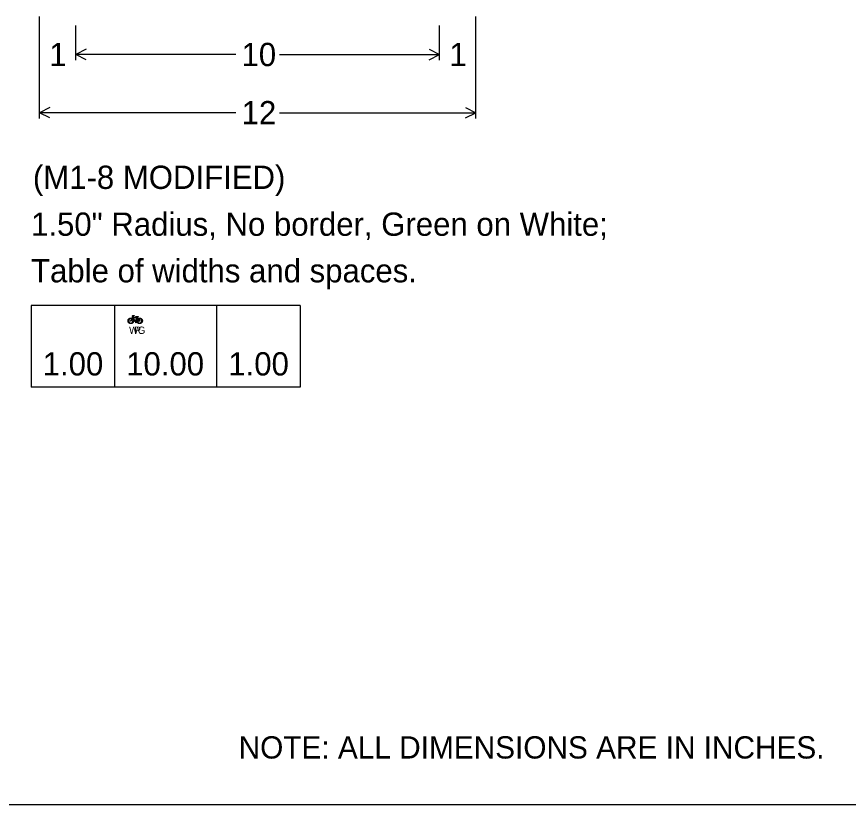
# Model space of a CAD drawing. Extents: x -39.4 to 36.9, y -12.9 to 28.
# Drawn here: x -12.53 to -7.31, y -1.19 to 3.76 of the extents above; entities that cross this region are included whole.
import ezdxf

# ---------------------------------------------------------------- set-up
doc = ezdxf.new("R2010")
doc.units = 0
doc.layers.add('PM_P_Text', color=7, linetype='Continuous')
doc.layers.add('SH_Text', color=7, linetype='Continuous')

msp = doc.modelspace()

# ---------------------------------------------------------------- linework, layer by layer
at = {"layer": 'PM_P_Text'}
for p, q in [((-12.3914, 3.1166), (-12.3914, 3.7566)), ((-9.6482, 3.1166), (-9.6482, 3.7566)), ((-12.3914, 3.4823), (-12.3914, 3.7018)), ((-12.1628, 3.4823), (-12.1628, 3.7018)), ((-9.8768, 3.4823), (-9.8768, 3.7018)), ((-9.8768, 3.4823), (-9.8768, 3.7018)), ((-9.6482, 3.4823), (-9.6482, 3.7018)), ((-12.0973, 3.5516), (-12.1628, 3.5189)), ((-11.1575, 3.5189), (-12.1628, 3.5189)), ((-12.0973, 3.4862), (-12.1628, 3.5189)), ((-10.8821, 3.5189), (-9.8768, 3.5189)), ((-9.9422, 3.5516), (-9.8768, 3.5189)), ((-9.9422, 3.4862), (-9.8768, 3.5189)), ((-12.3259, 3.1858), (-12.3914, 3.1531)), ((-11.1567, 3.1531), (-12.3914, 3.1531)), ((-12.3259, 3.1204), (-12.3914, 3.1531)), ((-10.8828, 3.1531), (-9.6482, 3.1531)), ((-9.7136, 3.1858), (-9.6482, 3.1531)), ((-9.7136, 3.1204), (-9.6482, 3.1531)), ((-12.4437, 1.9405), (-12.4437, 1.4284)), ((-10.7524, 1.9405), (-12.4437, 1.9405)), ((-11.919, 1.9405), (-11.919, 1.4284)), ((-11.2771, 1.9405), (-11.2771, 1.4284)), ((-10.7524, 1.9405), (-10.7524, 1.4284)), ((-10.7524, 1.4284), (-12.4437, 1.4284))]:
    msp.add_line(p, q, dxfattribs=at)
for points in [[(-11.8231, 1.8285), (-11.8236, 1.8287), (-11.8241, 1.8289), (-11.8246, 1.8291), (-11.8251, 1.8294), (-11.8256, 1.8297), (-11.8261, 1.83), (-11.8265, 1.8303), (-11.827, 1.8306), (-11.8275, 1.831), (-11.8279, 1.8313), (-11.8284, 1.8317), (-11.8288, 1.8321), (-11.8292, 1.8325), (-11.8296, 1.833), (-11.8301, 1.8334), (-11.8304, 1.8338), (-11.8308, 1.8343), (-11.8311, 1.8348), (-11.8315, 1.8352), (-11.8318, 1.8357), (-11.8321, 1.8362), (-11.8323, 1.8367), (-11.8326, 1.8372), (-11.8328, 1.8377), (-11.8331, 1.8382), (-11.8333, 1.8387), (-11.8335, 1.8392), (-11.8336, 1.8398), (-11.8338, 1.8403), (-11.8339, 1.8409), (-11.834, 1.8414), (-11.8341, 1.842), (-11.8342, 1.8426), (-11.8343, 1.8432), (-11.8343, 1.8437), (-11.8343, 1.8443), (-11.8343, 1.8449), (-11.8343, 1.8455), (-11.8343, 1.8461), (-11.8343, 1.8467), (-11.8342, 1.8473), (-11.8341, 1.8479), (-11.834, 1.8484), (-11.8339, 1.849), (-11.8338, 1.8495), (-11.8336, 1.8501), (-11.8335, 1.8506), (-11.8333, 1.8511), (-11.8331, 1.8517), (-11.8328, 1.8522), (-11.8326, 1.8527), (-11.8323, 1.8532), (-11.8321, 1.8536), (-11.8318, 1.8541), (-11.8315, 1.8546), (-11.8311, 1.8551), (-11.8308, 1.8555), (-11.8304, 1.856), (-11.83, 1.8565), (-11.8296, 1.8569), (-11.8292, 1.8573), (-11.8288, 1.8577), (-11.8284, 1.8581), (-11.8279, 1.8585), (-11.8275, 1.8589), (-11.827, 1.8592), (-11.8265, 1.8596), (-11.8261, 1.8599), (-11.8256, 1.8602), (-11.8251, 1.8605), (-11.8246, 1.8607), (-11.8241, 1.861), (-11.8236, 1.8612), (-11.8231, 1.8614), (-11.8225, 1.8616), (-11.822, 1.8617), (-11.8215, 1.8619), (-11.8209, 1.862), (-11.8204, 1.8622), (-11.8198, 1.8622), (-11.8192, 1.8623), (-11.8187, 1.8624), (-11.8181, 1.8624), (-11.8175, 1.8625), (-11.8169, 1.8625), (-11.8159, 1.8624), (-11.815, 1.8624), (-11.814, 1.8622), (-11.8131, 1.8621), (-11.8122, 1.8618), (-11.8113, 1.8615), (-11.8104, 1.8612), (-11.8095, 1.8608), (-11.8087, 1.8603), (-11.8043, 1.8734), (-11.8045, 1.8735), (-11.8047, 1.8737), (-11.8049, 1.874), (-11.8052, 1.8743), (-11.8055, 1.8747)], [(-11.828, 1.8535), (-11.8283, 1.853), (-11.8286, 1.8525), (-11.8289, 1.852), (-11.8292, 1.8516), (-11.8295, 1.851), (-11.8297, 1.8505), (-11.8299, 1.85), (-11.8301, 1.8495), (-11.8303, 1.8489), (-11.8305, 1.8484), (-11.8306, 1.8478), (-11.8307, 1.8472), (-11.8308, 1.8467), (-11.8308, 1.8461), (-11.8309, 1.8455), (-11.8309, 1.8449), (-11.8309, 1.8443), (-11.8308, 1.8437), (-11.8308, 1.8431), (-11.8307, 1.8425), (-11.8306, 1.8419), (-11.8305, 1.8414), (-11.8303, 1.8408), (-11.8301, 1.8403), (-11.8299, 1.8397), (-11.8297, 1.8392), (-11.8295, 1.8387), (-11.8292, 1.8382), (-11.8289, 1.8377), (-11.8286, 1.8372), (-11.8283, 1.8368), (-11.828, 1.8363), (-11.8276, 1.8358), (-11.8272, 1.8354), (-11.8268, 1.8349), (-11.8263, 1.8345), (-11.8259, 1.8341), (-11.8254, 1.8338), (-11.825, 1.8334), (-11.8245, 1.8331), (-11.824, 1.8328), (-11.8235, 1.8325), (-11.823, 1.8322), (-11.8225, 1.832), (-11.822, 1.8318), (-11.8214, 1.8316), (-11.8209, 1.8314), (-11.8203, 1.8312), (-11.8198, 1.8311), (-11.8192, 1.831), (-11.8187, 1.8309), (-11.8181, 1.8309), (-11.8175, 1.8309), (-11.8168, 1.8308), (-11.8163, 1.8309), (-11.8157, 1.8309), (-11.8151, 1.8309), (-11.8145, 1.831), (-11.8139, 1.8311), (-11.8134, 1.8312), (-11.8128, 1.8314), (-11.8123, 1.8316), (-11.8118, 1.8317), (-11.8112, 1.832), (-11.8107, 1.8322), (-11.8102, 1.8325), (-11.8097, 1.8328), (-11.8093, 1.8331), (-11.8088, 1.8334), (-11.8083, 1.8337), (-11.8079, 1.8341), (-11.8074, 1.8345), (-11.807, 1.8349), (-11.8066, 1.8354), (-11.8062, 1.8358), (-11.8058, 1.8363), (-11.8054, 1.8367), (-11.8051, 1.8372), (-11.8048, 1.8377), (-11.8045, 1.8382), (-11.8043, 1.8387), (-11.804, 1.8392), (-11.8038, 1.8397), (-11.8036, 1.8403), (-11.8034, 1.8408), (-11.8033, 1.8413), (-11.8032, 1.8419), (-11.8031, 1.8424), (-11.803, 1.843), (-11.8029, 1.8436), (-11.8029, 1.8442), (-11.8029, 1.8448), (-11.8029, 1.8454), (-11.8029, 1.846), (-11.803, 1.8465), (-11.8031, 1.8471), (-11.8032, 1.8476), (-11.8032, 1.8482), (-11.8034, 1.8487), (-11.8035, 1.8492)], [(-11.8074, 1.8551), (-11.8075, 1.8546), (-11.8077, 1.8542), (-11.8079, 1.8538), (-11.808, 1.8535), (-11.8081, 1.8532), (-11.8082, 1.853), (-11.8082, 1.8528), (-11.8083, 1.8527), (-11.8083, 1.8527), (-11.8088, 1.8518), (-11.8095, 1.8508), (-11.8101, 1.85), (-11.8108, 1.8491), (-11.8117, 1.8481), (-11.8119, 1.8479), (-11.8121, 1.8477), (-11.8124, 1.8474), (-11.8128, 1.8471), (-11.8132, 1.8467), (-11.8137, 1.8462), (-11.814, 1.8459), (-11.8143, 1.8456), (-11.8146, 1.8453), (-11.8147, 1.8452), (-11.8148, 1.8451), (-11.8149, 1.845), (-11.815, 1.8442), (-11.8155, 1.8435), (-11.8161, 1.8431), (-11.8169, 1.8429), (-11.8175, 1.8431), (-11.8181, 1.8434), (-11.8185, 1.8439), (-11.8187, 1.8446), (-11.8186, 1.8449), (-11.8186, 1.8452), (-11.8185, 1.8455), (-11.8183, 1.8458), (-11.8182, 1.846), (-11.8179, 1.8462), (-11.8177, 1.8464), (-11.8174, 1.8465), (-11.8171, 1.8466), (-11.8167, 1.8467), (-11.8163, 1.8469), (-11.8159, 1.8472), (-11.8154, 1.8476), (-11.815, 1.848), (-11.8145, 1.8486), (-11.814, 1.8492), (-11.8136, 1.8496), (-11.8133, 1.8501), (-11.8128, 1.8508), (-11.8123, 1.8515), (-11.8117, 1.8523), (-11.8115, 1.8525), (-11.8113, 1.853), (-11.811, 1.8535), (-11.8108, 1.8542), (-11.8107, 1.8543), (-11.8107, 1.8544), (-11.8106, 1.8546), (-11.8106, 1.8548), (-11.8105, 1.8551), (-11.8104, 1.8554), (-11.8103, 1.8557), (-11.8102, 1.8561), (-11.81, 1.8566), (-11.8099, 1.8571), (-11.8107, 1.8575), (-11.8115, 1.8579), (-11.8124, 1.8582), (-11.8132, 1.8584), (-11.8141, 1.8587), (-11.815, 1.8588), (-11.8159, 1.8589), (-11.8168, 1.8589), (-11.8174, 1.8589), (-11.8181, 1.8589), (-11.8186, 1.8588), (-11.8192, 1.8587), (-11.8198, 1.8586), (-11.8203, 1.8585), (-11.8209, 1.8584), (-11.8214, 1.8582), (-11.822, 1.858), (-11.8225, 1.8578), (-11.823, 1.8575), (-11.8235, 1.8573), (-11.824, 1.857), (-11.8245, 1.8567), (-11.825, 1.8563), (-11.8254, 1.856), (-11.8259, 1.8556), (-11.8263, 1.8552), (-11.8268, 1.8548), (-11.8272, 1.8544), (-11.8276, 1.8539), (-11.828, 1.8535)], [(-11.7867, 1.8383), (-11.7872, 1.8384), (-11.7876, 1.8387), (-11.7879, 1.839), (-11.7882, 1.8394), (-11.7883, 1.8399), (-11.7884, 1.8405), (-11.7884, 1.841), (-11.8057, 1.86), (-11.8061, 1.8587), (-11.8057, 1.8584), (-11.8053, 1.858), (-11.8049, 1.8577), (-11.8045, 1.8573), (-11.8042, 1.857), (-11.8038, 1.8566), (-11.8035, 1.8562), (-11.8032, 1.8558), (-11.8029, 1.8555), (-11.8026, 1.8551), (-11.8023, 1.8547), (-11.802, 1.8543), (-11.8018, 1.8539), (-11.8015, 1.8535), (-11.8013, 1.853), (-11.8011, 1.8526), (-11.8009, 1.8522), (-11.8007, 1.8517), (-11.8005, 1.8513), (-11.8004, 1.8508), (-11.8002, 1.8504), (-11.8001, 1.8499), (-11.8, 1.8494), (-11.7998, 1.849), (-11.7997, 1.8485), (-11.7997, 1.848), (-11.7996, 1.8475), (-11.7995, 1.847), (-11.7995, 1.8465), (-11.7994, 1.846), (-11.7994, 1.8454), (-11.7994, 1.8449), (-11.7994, 1.8443), (-11.7994, 1.8437), (-11.7995, 1.8431), (-11.7996, 1.8425), (-11.7996, 1.842), (-11.7997, 1.8414), (-11.7998, 1.8408), (-11.8, 1.8403), (-11.8001, 1.8398), (-11.8003, 1.8392), (-11.8005, 1.8387), (-11.8007, 1.8382), (-11.8009, 1.8377), (-11.8012, 1.8372), (-11.8014, 1.8367), (-11.8017, 1.8362), (-11.802, 1.8357), (-11.8023, 1.8352), (-11.8026, 1.8347), (-11.803, 1.8343), (-11.8033, 1.8338), (-11.8037, 1.8334), (-11.8041, 1.833), (-11.8045, 1.8325), (-11.805, 1.8321), (-11.8054, 1.8317), (-11.8058, 1.8313), (-11.8063, 1.831), (-11.8067, 1.8306), (-11.8072, 1.8303), (-11.8077, 1.83), (-11.8082, 1.8297), (-11.8087, 1.8294), (-11.8092, 1.8291), (-11.8097, 1.8289), (-11.8102, 1.8287), (-11.8107, 1.8285), (-11.8112, 1.8283), (-11.8117, 1.8281), (-11.8123, 1.828), (-11.8128, 1.8278), (-11.8134, 1.8277), (-11.814, 1.8276), (-11.8145, 1.8275), (-11.8151, 1.8275), (-11.8157, 1.8274), (-11.8163, 1.8274), (-11.8169, 1.8274), (-11.8175, 1.8274), (-11.8181, 1.8274), (-11.8187, 1.8275), (-11.8192, 1.8275), (-11.8198, 1.8276), (-11.8204, 1.8277), (-11.8209, 1.8278), (-11.8215, 1.828), (-11.822, 1.8281), (-11.8226, 1.8283), (-11.8231, 1.8285)], [(-11.8035, 1.8492), (-11.8037, 1.8497), (-11.8039, 1.8502), (-11.8041, 1.8507), (-11.8043, 1.8512), (-11.8046, 1.8516), (-11.8049, 1.8521), (-11.8052, 1.8525), (-11.8055, 1.853), (-11.8058, 1.8534), (-11.8062, 1.8539), (-11.8065, 1.8543), (-11.8069, 1.8547), (-11.8074, 1.8551), (-11.8074, 1.8551)], [(-11.8055, 1.8747), (-11.8059, 1.8751), (-11.8064, 1.8756), (-11.8031, 1.8787), (-11.7953, 1.8787), (-11.7953, 1.8778), (-11.7953, 1.877), (-11.7953, 1.8765), (-11.8018, 1.8765), (-11.8029, 1.8753), (-11.8009, 1.8733), (-11.803, 1.8672), (-11.7789, 1.8672), (-11.7786, 1.868), (-11.7783, 1.8688), (-11.7786, 1.8688), (-11.779, 1.8689), (-11.7794, 1.869), (-11.78, 1.8691), (-11.7807, 1.8692), (-11.7813, 1.8694), (-11.7821, 1.8696), (-11.7831, 1.8699), (-11.7842, 1.8703), (-11.7846, 1.8706), (-11.7849, 1.871), (-11.785, 1.8713), (-11.7849, 1.8717), (-11.7848, 1.8719), (-11.7845, 1.872), (-11.7842, 1.8721), (-11.7709, 1.8729), (-11.7706, 1.8729), (-11.7703, 1.8729), (-11.7701, 1.8728), (-11.77, 1.8726), (-11.7699, 1.8724), (-11.7698, 1.8721), (-11.7699, 1.8718), (-11.77, 1.8715), (-11.7703, 1.8711), (-11.7707, 1.8707), (-11.7711, 1.8704), (-11.7717, 1.8701), (-11.7722, 1.8698), (-11.7729, 1.8695), (-11.7736, 1.8692), (-11.7745, 1.8689), (-11.7749, 1.8688), (-11.7753, 1.8686), (-11.7761, 1.8662), (-11.7757, 1.8657), (-11.7754, 1.8653), (-11.775, 1.8648), (-11.7746, 1.8643), (-11.7742, 1.8637), (-11.7737, 1.8631), (-11.7732, 1.8625), (-11.7727, 1.8618), (-11.7722, 1.8611), (-11.7716, 1.8604), (-11.771, 1.8596), (-11.771, 1.8596)], [(-11.7797, 1.8645), (-11.8041, 1.8645), (-11.8045, 1.8632), (-11.7877, 1.8445), (-11.7882, 1.8472), (-11.7895, 1.8472), (-11.7895, 1.8487), (-11.7855, 1.8487), (-11.7855, 1.8472), (-11.7866, 1.8472), (-11.7865, 1.8465), (-11.7864, 1.8459), (-11.7863, 1.8455), (-11.7862, 1.8451), (-11.7861, 1.8447), (-11.7861, 1.8445), (-11.7797, 1.8645), (-11.7797, 1.8645)], [(-11.7558, 1.8285), (-11.7563, 1.8283), (-11.7568, 1.8282), (-11.7574, 1.828), (-11.7579, 1.8279), (-11.7585, 1.8278), (-11.7591, 1.8277), (-11.7596, 1.8277), (-11.7602, 1.8276), (-11.7608, 1.8276), (-11.7614, 1.8276), (-11.7622, 1.8276), (-11.7629, 1.8277), (-11.7636, 1.8277), (-11.7643, 1.8278), (-11.765, 1.8279), (-11.7657, 1.8281), (-11.7664, 1.8283), (-11.7671, 1.8285), (-11.7677, 1.8287), (-11.7684, 1.829), (-11.769, 1.8293), (-11.7696, 1.8296), (-11.7703, 1.8299), (-11.7709, 1.8303), (-11.7714, 1.8307), (-11.772, 1.8312), (-11.7726, 1.8316), (-11.7732, 1.8321), (-11.7737, 1.8326), (-11.7742, 1.8331), (-11.7746, 1.8336), (-11.7751, 1.8341), (-11.7755, 1.8347), (-11.7759, 1.8352), (-11.7763, 1.8358), (-11.7767, 1.8364), (-11.777, 1.8371), (-11.7773, 1.8377), (-11.7775, 1.8383), (-11.7778, 1.839), (-11.7781, 1.8397), (-11.7783, 1.8403), (-11.7789, 1.8402), (-11.7797, 1.8401), (-11.7806, 1.84), (-11.7815, 1.8398), (-11.7825, 1.8396), (-11.7835, 1.8394), (-11.7838, 1.8391), (-11.7842, 1.8387), (-11.7844, 1.8386), (-11.7847, 1.8385), (-11.7847, 1.8385), (-11.7847, 1.8384), (-11.7847, 1.8384), (-11.7847, 1.8383), (-11.7846, 1.8382), (-11.7846, 1.8381), (-11.7846, 1.8379), (-11.7845, 1.8377), (-11.7845, 1.8375), (-11.7844, 1.8373), (-11.7844, 1.8371), (-11.7843, 1.8368), (-11.7842, 1.8365), (-11.7842, 1.8362), (-11.7841, 1.8359), (-11.784, 1.8356), (-11.7839, 1.8352), (-11.7838, 1.8348), (-11.7837, 1.8344), (-11.7836, 1.8339), (-11.7835, 1.8335), (-11.7821, 1.8335), (-11.7821, 1.8318), (-11.7861, 1.8318), (-11.7861, 1.8335), (-11.7853, 1.8335), (-11.7853, 1.8335), (-11.7853, 1.8335), (-11.7853, 1.8336), (-11.7853, 1.8336), (-11.7853, 1.8337), (-11.7853, 1.8339), (-11.7854, 1.834), (-11.7854, 1.8342), (-11.7855, 1.8343), (-11.7855, 1.8345), (-11.7855, 1.8348), (-11.7856, 1.835), (-11.7857, 1.8353), (-11.7857, 1.8356), (-11.7858, 1.8359), (-11.7859, 1.8362), (-11.786, 1.8365), (-11.7861, 1.8369), (-11.7861, 1.8373), (-11.7863, 1.8377), (-11.7863, 1.8382), (-11.7867, 1.8383)], [(-11.7835, 1.8425), (-11.7789, 1.8432), (-11.7789, 1.8442), (-11.7789, 1.845), (-11.7789, 1.8456), (-11.7789, 1.8461), (-11.7789, 1.8467), (-11.7788, 1.8473), (-11.7787, 1.8478), (-11.7786, 1.8484), (-11.7785, 1.8489), (-11.7784, 1.8494), (-11.7783, 1.85), (-11.7781, 1.8505), (-11.7779, 1.851), (-11.7777, 1.8515), (-11.7775, 1.852), (-11.7773, 1.8525), (-11.7771, 1.8529), (-11.7768, 1.8534), (-11.7765, 1.8539), (-11.7762, 1.8544), (-11.7759, 1.8548), (-11.7756, 1.8552), (-11.7753, 1.8557), (-11.7749, 1.8561), (-11.7745, 1.8565), (-11.7741, 1.857), (-11.7737, 1.8574), (-11.7733, 1.8578), (-11.7771, 1.8628), (-11.7835, 1.8425), (-11.7835, 1.8425)], [(-11.7642, 1.846), (-11.7643, 1.8462), (-11.7645, 1.8465), (-11.7647, 1.8467), (-11.7649, 1.847), (-11.7652, 1.8473), (-11.7654, 1.8476), (-11.7657, 1.8479), (-11.7659, 1.8483), (-11.7662, 1.8486), (-11.7665, 1.849), (-11.7668, 1.8494), (-11.7671, 1.8498), (-11.7675, 1.8503), (-11.7678, 1.8507), (-11.7682, 1.8512), (-11.7685, 1.8517), (-11.7689, 1.8522), (-11.7693, 1.8527), (-11.7697, 1.8532), (-11.7702, 1.8538), (-11.7706, 1.8544), (-11.771, 1.8549), (-11.7715, 1.8545), (-11.7719, 1.854), (-11.7723, 1.8536), (-11.7726, 1.8531), (-11.773, 1.8526), (-11.7733, 1.8522), (-11.7736, 1.8517), (-11.7738, 1.8512), (-11.7741, 1.8507), (-11.7743, 1.8501), (-11.7745, 1.8496), (-11.7747, 1.8491), (-11.7749, 1.8485), (-11.775, 1.848), (-11.7751, 1.8474), (-11.7752, 1.8468), (-11.7752, 1.8462), (-11.7753, 1.8456), (-11.7753, 1.845), (-11.7753, 1.8444), (-11.7752, 1.8439), (-11.7697, 1.8449), (-11.7642, 1.846), (-11.7642, 1.846)], [(-11.7686, 1.8568), (-11.7614, 1.8471), (-11.7613, 1.847), (-11.7612, 1.8469), (-11.7609, 1.8467), (-11.7606, 1.8464), (-11.7602, 1.8462), (-11.7599, 1.8459), (-11.7598, 1.8454), (-11.7597, 1.845), (-11.7597, 1.8446), (-11.7598, 1.8443), (-11.7598, 1.8441), (-11.7599, 1.8439), (-11.7601, 1.8437), (-11.7602, 1.8435), (-11.7604, 1.8433), (-11.7606, 1.8432), (-11.7609, 1.8432), (-11.7612, 1.8431), (-11.7615, 1.8431), (-11.7618, 1.8431), (-11.7621, 1.8432), (-11.7626, 1.8433), (-11.7629, 1.8434), (-11.763, 1.8433), (-11.7631, 1.8433), (-11.7632, 1.8433), (-11.7633, 1.8433), (-11.7634, 1.8433), (-11.7636, 1.8432), (-11.7637, 1.8432), (-11.7639, 1.8432), (-11.764, 1.8431), (-11.7642, 1.8431), (-11.7644, 1.8431), (-11.7646, 1.843), (-11.7649, 1.843), (-11.7651, 1.8429), (-11.7653, 1.8429), (-11.7656, 1.8428), (-11.7659, 1.8428), (-11.7661, 1.8427), (-11.7664, 1.8427), (-11.7667, 1.8426), (-11.7671, 1.8426), (-11.7674, 1.8425), (-11.7677, 1.8424), (-11.7681, 1.8424), (-11.7684, 1.8423), (-11.7688, 1.8422), (-11.7692, 1.8421), (-11.7696, 1.8421), (-11.77, 1.842), (-11.7704, 1.8419), (-11.7709, 1.8418), (-11.7713, 1.8417), (-11.7717, 1.8416), (-11.7722, 1.8415), (-11.7727, 1.8414), (-11.7732, 1.8413), (-11.7737, 1.8412), (-11.7742, 1.8411), (-11.7747, 1.841), (-11.7745, 1.8403), (-11.7742, 1.8396), (-11.7739, 1.839), (-11.7735, 1.8383), (-11.7732, 1.8377), (-11.7728, 1.8371), (-11.7723, 1.8365), (-11.7719, 1.836), (-11.7714, 1.8354), (-11.7709, 1.8349), (-11.7703, 1.8344), (-11.7697, 1.8339), (-11.769, 1.8335), (-11.7684, 1.8331), (-11.7678, 1.8327), (-11.7671, 1.8324), (-11.7664, 1.8321), (-11.7658, 1.8318), (-11.7651, 1.8316), (-11.7644, 1.8315), (-11.7636, 1.8313), (-11.7629, 1.8312), (-11.7622, 1.8312), (-11.7614, 1.8312), (-11.7608, 1.8312), (-11.7602, 1.8312), (-11.7596, 1.8313), (-11.7591, 1.8313), (-11.7585, 1.8314), (-11.7579, 1.8316), (-11.7574, 1.8317), (-11.7568, 1.8319), (-11.7563, 1.8321), (-11.7558, 1.8323), (-11.7553, 1.8325), (-11.7548, 1.8328)], [(-11.771, 1.8596), (-11.7703, 1.86), (-11.7696, 1.8604), (-11.7689, 1.8608), (-11.7682, 1.8611), (-11.7675, 1.8614), (-11.7668, 1.8616), (-11.7661, 1.8619), (-11.7653, 1.8621), (-11.7646, 1.8622), (-11.7638, 1.8623), (-11.763, 1.8624), (-11.7622, 1.8624), (-11.7614, 1.8625), (-11.7608, 1.8625), (-11.7602, 1.8624), (-11.7596, 1.8624), (-11.7591, 1.8623), (-11.7585, 1.8622), (-11.7579, 1.8622), (-11.7574, 1.862), (-11.7568, 1.8619), (-11.7563, 1.8618), (-11.7558, 1.8616), (-11.7552, 1.8614), (-11.7547, 1.8612), (-11.7542, 1.861), (-11.7537, 1.8607), (-11.7532, 1.8605), (-11.7527, 1.8602), (-11.7522, 1.8599), (-11.7518, 1.8596), (-11.7513, 1.8593), (-11.7508, 1.8589), (-11.7504, 1.8586), (-11.7499, 1.8582), (-11.7495, 1.8578), (-11.7491, 1.8573), (-11.7487, 1.8569), (-11.7483, 1.8565), (-11.7479, 1.856), (-11.7475, 1.8556), (-11.7472, 1.8551), (-11.7468, 1.8547), (-11.7465, 1.8542), (-11.7462, 1.8537), (-11.746, 1.8532), (-11.7457, 1.8527), (-11.7455, 1.8522), (-11.7452, 1.8517), (-11.745, 1.8512), (-11.7448, 1.8507), (-11.7447, 1.8501), (-11.7445, 1.8496), (-11.7444, 1.8491), (-11.7443, 1.8485), (-11.7442, 1.848), (-11.7441, 1.8474), (-11.744, 1.8468), (-11.744, 1.8462), (-11.744, 1.8456), (-11.7439, 1.845), (-11.744, 1.8444), (-11.744, 1.8438), (-11.744, 1.8433), (-11.7441, 1.8427), (-11.7442, 1.8421), (-11.7443, 1.8416), (-11.7444, 1.841), (-11.7445, 1.8405), (-11.7447, 1.8399), (-11.7448, 1.8394), (-11.745, 1.8389), (-11.7452, 1.8383), (-11.7455, 1.8378), (-11.7457, 1.8373), (-11.746, 1.8368), (-11.7462, 1.8363), (-11.7465, 1.8359), (-11.7468, 1.8354), (-11.7472, 1.8349), (-11.7475, 1.8345), (-11.7479, 1.834), (-11.7483, 1.8336), (-11.7487, 1.8331), (-11.7491, 1.8327), (-11.7495, 1.8323), (-11.7499, 1.8319), (-11.7504, 1.8315), (-11.7508, 1.8311), (-11.7513, 1.8308), (-11.7518, 1.8305), (-11.7522, 1.8301), (-11.7527, 1.8299), (-11.7532, 1.8296), (-11.7537, 1.8293), (-11.7542, 1.8291), (-11.7547, 1.8289), (-11.7552, 1.8287), (-11.7558, 1.8285)], [(-11.7548, 1.8328), (-11.7543, 1.833), (-11.7538, 1.8333), (-11.7533, 1.8337), (-11.7529, 1.834), (-11.7524, 1.8344), (-11.752, 1.8348), (-11.7516, 1.8352), (-11.7511, 1.8356), (-11.7507, 1.8361), (-11.7504, 1.8365), (-11.75, 1.837), (-11.7497, 1.8375), (-11.7494, 1.8379), (-11.7491, 1.8384), (-11.7488, 1.8389), (-11.7486, 1.8394), (-11.7484, 1.84), (-11.7482, 1.8405), (-11.748, 1.841), (-11.7479, 1.8416), (-11.7478, 1.8421), (-11.7476, 1.8427), (-11.7476, 1.8432), (-11.7475, 1.8438), (-11.7475, 1.8444), (-11.7475, 1.845), (-11.7475, 1.8456), (-11.7475, 1.8462), (-11.7476, 1.8468), (-11.7476, 1.8474), (-11.7478, 1.8479), (-11.7479, 1.8485), (-11.748, 1.849), (-11.7482, 1.8496), (-11.7484, 1.8501), (-11.7486, 1.8506), (-11.7488, 1.8511), (-11.7491, 1.8516), (-11.7494, 1.8521), (-11.7497, 1.8526), (-11.75, 1.853), (-11.7504, 1.8535), (-11.7507, 1.8539), (-11.7511, 1.8544), (-11.7516, 1.8548), (-11.752, 1.8552), (-11.7524, 1.8556), (-11.7529, 1.856), (-11.7534, 1.8564), (-11.7538, 1.8567), (-11.7543, 1.857), (-11.7548, 1.8573), (-11.7553, 1.8575), (-11.7558, 1.8578), (-11.7563, 1.858), (-11.7569, 1.8582), (-11.7574, 1.8584), (-11.7579, 1.8585), (-11.7585, 1.8586), (-11.7591, 1.8587), (-11.7596, 1.8588), (-11.7602, 1.8589), (-11.7608, 1.8589), (-11.7614, 1.8589), (-11.7623, 1.8589), (-11.7631, 1.8588), (-11.7639, 1.8587), (-11.7648, 1.8585), (-11.7656, 1.8583), (-11.7664, 1.858), (-11.7671, 1.8576), (-11.7679, 1.8573), (-11.7686, 1.8568), (-11.7686, 1.8568)]]:
    msp.add_lwpolyline(points, dxfattribs=at)
at = {"layer": 'SH_Text'}
msp.add_line((-14.3713, -1.1935), (16.1287, -1.1935), dxfattribs=at)

# ---------------------------------------------------------------- texts
at = {"layer": 'PM_P_Text'}
for s, height, p in [('1', 0.1463, (-12.329, 3.4457)), ('10', 0.1463, (-11.1209, 3.4457)), ('1', 0.1463, (-9.8144, 3.4457)), ('12', 0.1463, (-11.1201, 3.08)), ('(M1-8 MODIFIED)', 0.146304, (-12.432, 2.674)), ('1.50" Radius, No border, Green on White; ', 0.146304, (-12.4437, 2.3794)), ('Table of widths and spaces.', 0.146304, (-12.4437, 2.0868)), ('W', 0.0457, (-11.8275, 1.7633)), ('R', 0.0457, (-11.7955, 1.7633)), ('G', 0.0457, (-11.7728, 1.7633)), ('1.00', 0.1463, (-12.3705, 1.5016)), ('1.00', 0.1463, (-12.3705, 1.5016)), ('10.00', 0.1463, (-11.8458, 1.5016)), ('1.00', 0.1463, (-11.2039, 1.5016)), ('NOTE: ALL DIMENSIONS ARE IN INCHES.', 0.14, (-11.139, -0.9056))]:
    msp.add_text(s, height=height, dxfattribs=at).set_placement(p)

doc.saveas('drawing.dxf')
